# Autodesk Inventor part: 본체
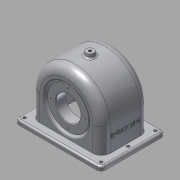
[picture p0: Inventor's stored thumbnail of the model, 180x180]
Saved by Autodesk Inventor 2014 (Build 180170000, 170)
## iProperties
Created: 2015-09
Part Number: 본체
Material: 알루미늄 6061
Document SubType Name: 판금
Designer: Owner
Density: 2.71 g/cm^3
Appearance: 알루미늄 - 평지
Sheet Metal Rule: 기본값
Mass: 676.854 g
Surface Area: 896.067 cm^2
Volume: 249.762 cm^3
Author: Owner
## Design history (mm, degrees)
sketch "스케치1"
  geometry: L1 (-57, 38.5)-(57, 38.5); L2 (57, 38.5)-(57, -38.5); L3 (57, -38.5)-(-57, -38.5); L4 (-57, -38.5)-(-57, 38.5); 1 further point
  constraints: 8 end point, 2 parallel, 1 horizontal, 1 perpendicular
  dimensions: "d2" = 77 distance of L1.end L2.end; "d3" = 38.5 distance from line of L1 point (0, 0); "d4" = 114 distance of L2.end L3.end; "d8" = 57 distance from line of point (0, 0) L4
extrude "돌출1" new body sketch "스케치1" distance "d9" = 47; taper "d10" = 0 deg
sketch "스케치2"
  geometry: L1 (114, 0)-(114, 47) reference; L2 (0, 47)-(114, 47) reference; L3 (0, 47)-(114, 47); A1 r 57 centre (57, 47) between (114, 47) and (0, 47); 1 further point
  constraints: 3 point on circle, 2 end point, 2 point on line, 1 centre point, 1 midpoint, 1 perpendicular
  dimensions: "d11" = 114 diameter of A1 (derived)
extrude "돌출2" join sketch "스케치2" distance "d12" = 77; taper "d13" = 0 deg
feature "쉘1" dims "d14" = 5
fillet "모깎기1" dims "d15" = 9
sketch "스케치3"
  geometry: C1 r 31 at (57, 47); A1 r 57 centre (57, 47) between (114, 47) and (0, 47) reference; 1 further point
  constraints: 1 centre point, 1 coincident
  dimensions: "d16" = 62 diameter of C1
extrude "돌출3" join sketch "스케치3" distance "d17" = 10; taper "d18" = 0 deg
hole "구멍1" diameter "d21" = 40; stored, may be unused: countersink angle "d25" = 90 deg, drill point angle "d27" = 0 deg; dims "d19" = 10, "d20" = 10, "d22" = 6, "d23" = 4, "d24" = 2, "d26" = 8
chamfer "모따기1" distance "d28" = 1; stored, may be unused: second distance "d29" = 2, angle "d30" = 45 deg
sketch "스케치4"
  geometry: C1 r 31 at (0, 0) reference; 2 further points
  constraints: 1 vertical alignment
  dimensions: "d31" = 24 distance of C1.centre point (0, 24)
hole "구멍2" sketch "스케치4" at (0, 24) diameter "d32" = 2.459; stored, may be unused: countersink angle "d36" = 90 deg, drill point angle "d38" = 118 deg; dims "d33" = 6, "d34" = 4, "d35" = 2, "d37" = 8
sketch "스케치6"
  geometry: L1 (0, 47)-(25.941, 47); L2 (33.5, 47)-(33.5, 90) reference; L3 (33.5, 67)-(19.5, 67); L4 (19.5, 67)-(19.5, 75); L5 (19.5, 75)-(33.5, 86.747); L6 (33.5, 86.747)-(33.5, 67); 1 further point
  constraints: 10 end point, 2 perpendicular, 2 point on line, 1 collinear, 1 horizontal
  dimensions: "d43" = 47 distance from line of L1 point (0, 0); "d44" = 56 diameter of L4.end L1; "d45" = 14 distance between parallel lines of L4 L2; "d46" = 50 deg angle of L4 L5; "d47" = 40 diameter of L3 L1
revolve "회전1" sketch "스케치6" stored, may be unused: angle "d48" = 90 deg
sketch "스케치7"
  geometry: C1 r 20 at (57, -47); A1 r 57 centre (57, -47) between (0, -47) and (114, -47) reference; 1 further point
  constraints: 1 centre point, 1 coincident
  dimensions: "d49" = 40 diameter of C1
extrude "돌출4" cut sketch "스케치7" stored distance "d50" = 5; taper "d51" = 0 deg
sketch "스케치9"
  geometry: L1 (0.962, 47)-(33.255, 47); L2 (38.5, 67)-(19.5, 67) reference; L3 (35.5, 67)-(35.5, 80); L4 (35.5, 80)-(34.611, 80); L5 (19.5, 75)-(33.5, 86.747) reference; L6 (34.29, 80.883)-(38.5, 84.416); L7 (38.5, 47)-(38.5, 104) reference; L8 (38.5, 84.416)-(38.5, 67); L9 (35.5, 67)-(38.5, 67); A1 r 0.5 centre (34.611, 80.5) between (34.29, 80.883) and (34.611, 80); 2 further points
  constraints: 12 end point, 3 point on line, 2 collinear, 2 perpendicular, 2 point on circle, 2 tangent, 1 centre point, 1 horizontal, 1 parallel
  dimensions: "d52" = 47 distance from line of point (0, 0) L1; "d53" = 66 diameter of point (33.237, 80) L1; "d54" = 3 distance between parallel lines of L7 L3; "d55" = 5 distance between parallel lines of L5 L6; "d57" = 0.5 radius of A1
revolve "회전2" sketch "스케치9" stored, may be unused: angle "d56" = 90 deg
chamfer "모따기2" distance "d58" = 1; stored, may be unused: second distance "d59" = 2, angle "d60" = 45 deg
chamfer "모따기3" distance "d61" = 1; stored, may be unused: second distance "d62" = 2, angle "d63" = 45 deg
node "작업 평면2"
sketch "스케치22"
  geometry: L1 (-70, 52)-(70, 52); L2 (70, 52)-(70, -52); L3 (70, -52)-(-70, -52); L4 (-70, -52)-(-70, 52); L5 (38.416, 38.5)-(-38.416, 38.5) reference; L6 (-57, -38.5)-(57, -38.5) reference; L7 (-57, -38.5)-(-57, 38.5) reference; L8 (57, 38.5)-(-57, 38.5) reference; L9 (57, 38.5)-(57, -38.5) reference; L10 (-57, 38.5)-(57, 38.5); L11 (57, 38.5)-(57, -38.5); L12 (57, -38.5)-(-57, -38.5); L13 (-57, -38.5)-(-57, 38.5); C1 r 2.5 at (-62, 44); C2 r 2.5 at (62, 44); C3 r 2.5 at (-62, 0); C4 r 2.5 at (62, 0); C5 r 2.5 at (-62, -44); C6 r 2.5 at (62, -44); 1 further point
  constraints: 16 end point, 6 centre point, 4 parallel, 3 horizontal, 2 perpendicular, 1 vertical, 10 other
  dimensions: "d131" = 140 distance of L1.start L1.end; "d132" = 104 distance of L1.end L2.end; "d133" = 70 distance from line of point (0, 0) L4; "d134" = 52 distance from line of point (0, 0) L1; "d135" = 5 diameter of C1; "d136" = 8 distance from line of L4 C1.centre; "d137" = 8 distance from line of L1 C1.centre; "d140" = 124 distance of C1.centre C2.centre; "d143" = 44 distance of C1.centre C3.centre
extrude "돌출8" join sketch "스케치22" distance "d146" = 7; taper "d147" = 0 deg
fillet "모깎기5" dims "d93" = 3
node "작업 평면1"
sketch "스케치12"
  geometry: C1 r 6 at (0, 0); 1 further point
  constraints: 1 centre point, 1 coincident
  dimensions: "d97" = 12 diameter of C1
extrude "돌출7" join sketch "스케치12" stored distance "d98" = 7; taper "d99" = 10 deg
fillet "모깎기8" dims "d100" = 3
hole "구멍3" diameter "d103" = 4.459; stored, may be unused: countersink angle "d107" = 90 deg, drill point angle "d109" = 118 deg; dims "d101" = 10, "d102" = 10, "d104" = 15, "d105" = 4, "d106" = 2, "d108" = 8
sketch "스케치16"
  geometry: C1 r 33 at (0, 0) reference; 2 further points
  constraints: 1 vertical alignment
  dimensions: "d113" = 28 distance of C1.centre point (0, -28)
hole "구멍4" sketch "스케치16" at (0, -28) diameter "d114" = 2.459; stored, may be unused: countersink angle "d118" = 90 deg, drill point angle "d120" = 118 deg; dims "d115" = 7, "d116" = 4, "d117" = 2, "d119" = 9
sketch "스케치20"
  geometry: L1 (-40, 77)-(0, 77) reference; 2 further points
  constraints: 1 other
  dimensions: "d126" = 30 distance of point (-47, 38.5) point (-17, 38.5); "d127" = 38.5 distance from line of L1 point (-17, 38.5)
feature "엠보싱2" sketch "스케치20" dims "d2" = 77, "d3" = 38.5, "d4" = 114, "d8" = 57, "d128" = 0.5, "d129" = 0
fillet "모깎기9" dims "d148" = 7
fillet "모깎기10" dims "d149" = 3
fillet "모깎기11" dims "d150" = 14
fillet "모깎기12" dims "d151" = 0.5
node "솔리드1"
pattern_circular "원형 패턴1" dims angle "d40" = 360 deg
pattern_circular "원형 패턴2" dims angle "d122" = 360 deg
node "투영된 루프1"
other parameters: "K계수" = 4.4, "BendRadius" = 0.5 (derived), "BendReliefWidth" = 0.5 (derived), "BendReliefDepth" = 0.25 (derived), "CornerReliefSize" = 2 (derived), "SeamGap" = 0.01, "MinimumRemnant" = 1 (derived), "TransitionRadius" = 0.5 (= BendRadius), "d130" = -7
